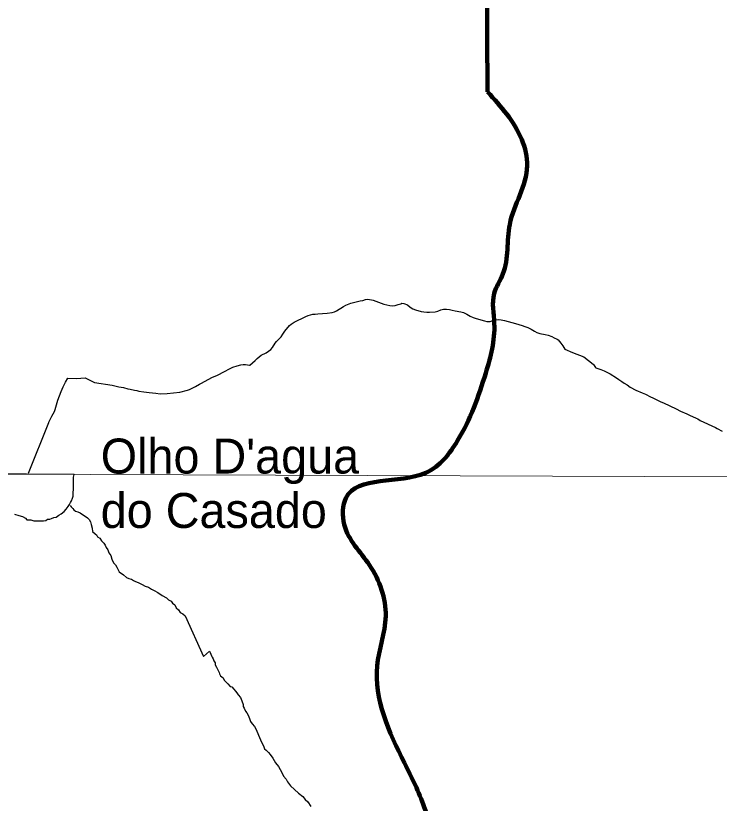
# Model space of a CAD drawing. Extents: x 553962 to 842807, y 8883888 to 9032388.
# Drawn here: x 628127 to 638188, y 8944931 to 8956199 of the extents above; entities that cross this region are included whole.
import ezdxf

# ---------------------------------------------------------------- set-up
doc = ezdxf.new("R2010")
doc.units = 0
doc.header["$LTSCALE"] = 20
for name, color, linetype, lineweight in [('1', 7, 'Continuous', 13), ('12', 7, 'Continuous', 25), ('21', 7, 'Continuous', 25), ('9', 7, 'Continuous', 90)]:
    doc.layers.add(name, color=color, linetype=linetype, lineweight=lineweight)
doc.layers.add('41', color=7, linetype='Continuous')

msp = doc.modelspace()

# ---------------------------------------------------------------- linework, layer by layer
at = {"layer": '1'}
msp.add_line((565315.27, 8949866.81), (791497.68, 8949052.23), dxfattribs=at)
at = {"layer": '12'}
for points in [[(631977.14, 8951685.31), (632043.77, 8951765.54), (632068.08, 8951787.61), (632108.71, 8951813.71), (632273.33, 8951897.11), (632308.21, 8951910.18), (632340.39, 8951920.25), (632377.33, 8951927.32), (632410.52, 8951931.38), (632445.52, 8951933.43), (632582.96, 8951943.67), (632651.08, 8951951.79), (632683.27, 8951961.85), (632714.52, 8951977.93), (632813.64, 8952039.18), (632846.33, 8952056.26), (632917.71, 8952084.42), (633052.14, 8952118.68), (633089.08, 8952126.75), (633126.77, 8952136.83), (633162.73, 8952142.23)], [(633162.73, 8952142.23), (633240.96, 8952131), (633351.39, 8952085.1), (633389.39, 8952073.15), (633475.96, 8952053.25), (633512.33, 8952049.3), (633554.83, 8952055.38), (633594.52, 8952068.46), (633634.89, 8952078.54), (633648.77, 8952084.57), (633676.33, 8952083.62), (633727.39, 8952060.66), (633770.14, 8952027.68), (633804.08, 8952004.69), (633842.58, 8951989.73), (633923.58, 8951967.83), (633963.14, 8951960.88), (634004.52, 8951957.94), (634042.96, 8951958), (634125.08, 8951962.14), (634165.58, 8951972.22), (634207.02, 8951990.31), (634246.58, 8951999.39), (634287.96, 8952002.46), (634328.46, 8951997.51), (634368.89, 8951987.56), (634409.46, 8951974.61), (634490.39, 8951962.71), (634530.83, 8951952.76), (634579.83, 8951930.81), (634627.89, 8951901.84), (634668.14, 8951883.87), (634709.77, 8951868.92), (634829.27, 8951833.05), (634866.14, 8951824.09)], [(634866.14, 8951824.09), (634873.39, 8951824.1), (634910.21, 8951826.17), (634950.71, 8951837.25), (634989.14, 8951847.32), (635028.08, 8951852.39), (635071.27, 8951849.46), (635114.64, 8951840.51), (635272.58, 8951793.69), (635367.21, 8951768.8), (635408.89, 8951751.84), (635451.39, 8951736.88), (635498.58, 8951712.92), (635544.21, 8951683.95), (635579.39, 8951665.97), (635619.89, 8951654.02), (635700.83, 8951640.13), (635740.46, 8951628.17), (635792.39, 8951609.22), (635828.71, 8951590.25), (635872.46, 8951570.29), (635883.64, 8951562.29), (635922.39, 8951513.28), (635950.14, 8951475.26), (635979.58, 8951429.24), (636087.14, 8951379.33), (636253.14, 8951319.5), (636386.46, 8951215.55), (636391.71, 8951209.55), (636419.71, 8951164.52), (636421.71, 8951160.52), (636421.71, 8951160.5), (636421.71, 8951160.52)], [(628309.19, 8949653.44), (628599.71, 8950377.92), (628601.33, 8950384.94), (628641.39, 8950470.13), (628663.02, 8950503.22), (628681.27, 8950538.3), (628691.77, 8950567.36), (628700.39, 8950599.43), (628710.96, 8950631.49), (628727.33, 8950696.62), (628774.64, 8950822.89), (628788.89, 8950855.97), (628806.89, 8950888.05), (628840.77, 8950956.21), (628872.21, 8951013.35), (628996.89, 8951009.54), (629121.21, 8951016.75), (629253.83, 8950950.85), (629505.89, 8950912.19), (629601.83, 8950889.31), (629665.71, 8950879.39), (629728.83, 8950861.46), (629762.52, 8950857.51), (629825.58, 8950843.59), (629857.52, 8950834.63), (629889.52, 8950829.67), (629956.46, 8950815.75), (630035.27, 8950806.86), (630130.21, 8950799), (630192.33, 8950791.09), (630294.14, 8950795.25), (630475.33, 8950814.57), (630582.08, 8950842.78), (630610.83, 8950852.85), (630639.64, 8950867.91), (630696.46, 8950894.05), (630755.08, 8950927.19), (630784.02, 8950940.26), (630880.83, 8950995.5), (630942.27, 8951026.64), (631001.89, 8951051.77), (631119.89, 8951113.06), (631172.39, 8951142.19), (631232.08, 8951169.32), (631292.58, 8951189.45), (631346.58, 8951202.56), (631380.39, 8951208.62), (631413.71, 8951209.67), (631469.39, 8951200.75), (631474.58, 8951200.75), (631552.96, 8951267.98), (631580.96, 8951297.07), (631608.21, 8951320.15), (631637.46, 8951342.23), (631707.21, 8951377.4), (631776.39, 8951422.58), (631796.77, 8951451.66), (631836.14, 8951514.82), (631854.46, 8951538.88), (631890.14, 8951572.99), (631921.39, 8951606.09), (631949.08, 8951643.2), (631977.14, 8951685.31), (631977.14, 8951685.31)], [(636421.71, 8951160.52), (636492.64, 8951137.59), (636543.77, 8951117.64), (636626.89, 8951075.71), (636719.46, 8951017.77), (636751.46, 8950995.78), (636795.33, 8950967.81), (636826.08, 8950942.82), (636870.71, 8950918.85), (636915.39, 8950886.87), (636996.52, 8950842.93), (637085.14, 8950803.01), (637131.58, 8950784.05), (637204.67, 8950745.08)], [(637204.67, 8950745.08), (637236.39, 8950731.89), (637342.11, 8950681.19), (637402.46, 8950654.15), (637429.51, 8950639.72), (637442.23, 8950635.25), (637481.26, 8950617.94), (637571.46, 8950574.99), (637632.67, 8950543.33), (637724.17, 8950501.81), (637761.89, 8950483.02), (637855.75, 8950440.22), (637882.16, 8950429.63), (637917.44, 8950409.53), (638133.95, 8950306.46), (638157.9, 8950291.91), (638228.47, 8950253.87)], [(628906.42, 8949193.41), (628921.28, 8949173.29), (628943.61, 8949150.61), (628955.96, 8949130.5), (628983.33, 8949110.29), (629015.78, 8949102.56), (629048.16, 8949084.82), (629080.52, 8949064.58), (629117.82, 8949036.8), (629155.19, 8949016.52), (629177.5, 8948991.34), (629197.27, 8948958.66), (629204.48, 8948921.06), (629221.57, 8948865.87), (629226.23, 8948820.78), (629261, 8948788), (629283.37, 8948770.33), (629298.17, 8948742.69), (629330.55, 8948724.95), (629352.77, 8948687.25), (629385.04, 8948654.49), (629404.81, 8948624.32), (629422.07, 8948591.66), (629441.82, 8948556.48), (629459.02, 8948516.31), (629488.7, 8948473.55), (629503.33, 8948423.38), (629522.94, 8948370.68), (629552.74, 8948342.94), (629572.48, 8948307.76), (629604.48, 8948239.96), (629669.18, 8948196.97)], [(629669.18, 8948196.97), (629708.91, 8948159.15), (629743.83, 8948146.4), (629783.77, 8948136.13), (629808.64, 8948118.44), (629841.06, 8948105.71), (629875.94, 8948087.95), (629898.37, 8948077.78), (629935.77, 8948062.52), (629978.08, 8948034.7), (630025.51, 8948021.87), (630067.81, 8947994.05), (630107.7, 8947976.26), (630157.49, 8947945.89), (630219.71, 8947905.42), (630281.98, 8947872.46), (630311.75, 8947839.72), (630351.65, 8947824.43), (630368.91, 8947791.77), (630401.25, 8947769.03), (630420.95, 8947728.84), (630455.72, 8947696.07), (630480.46, 8947660.85), (630515.32, 8947640.59), (630547.61, 8947610.34), (630810.81, 8947030.28)], [(630810.81, 8947030.28), (630898.94, 8947107.31), (630908.79, 8947087.21), (630916.1, 8947062.13), (630925.95, 8947042.04), (630938.28, 8947019.42), (630948.14, 8946999.33), (630960.41, 8946969.21), (630977.71, 8946941.56), (630979.96, 8946908.99), (630999.74, 8946878.82), (631016.95, 8946838.65), (631034.19, 8946803.49), (631041.54, 8946783.41), (631056.33, 8946755.77), (631091.1, 8946722.99), (631108.38, 8946692.84), (631140.62, 8946657.58), (631160.48, 8946637.42), (631192.71, 8946599.65), (631215.18, 8946594.49), (631247.46, 8946564.24), (631269.74, 8946534.05), (631289.58, 8946511.39), (631306.87, 8946483.73), (631339.08, 8946443.46), (631358.73, 8946395.76), (631378.36, 8946345.57), (631380.61, 8946313.01), (631395.46, 8946292.88), (631412.64, 8946250.21), (631432.44, 8946222.53), (631452.2, 8946189.86), (631469.37, 8946144.68), (631486.55, 8946102.01), (631508.81, 8946069.31), (631541.02, 8946029.05), (631560.76, 8945993.86), (631627.11, 8945838.21)], [(631627.11, 8945838.21), (631649.21, 8945785.49), (631668.97, 8945752.81), (631686.16, 8945710.14), (631706.01, 8945689.98), (631740.76, 8945654.69), (631765.56, 8945626.99), (631805.19, 8945576.66), (631822.46, 8945544), (631842.21, 8945511.32), (631884.31, 8945455.97), (631906.5, 8945413.26), (631938.61, 8945360.48), (631958.29, 8945317.78), (631995.48, 8945274.98), (632015.19, 8945234.79), (632057.3, 8945181.94), (632111.91, 8945126.5), (632171.55, 8945076.03), (632231.21, 8945028.07), (632268.38, 8944982.76), (632303.17, 8944952.49), (632347.65, 8944882.1)]]:
    msp.add_lwpolyline(points, dxfattribs=at)
at = {"layer": '21'}
msp.add_lwpolyline([(628110.58, 8949066.73), (628172.96, 8949048.88), (628225.36, 8949033.59), (628265.21, 8949010.86), (628287.56, 8948988.22), (628315.06, 8948988.07), (628342.54, 8948985.42), (628384.94, 8948970.19), (628409.94, 8948970.06), (628442.44, 8948969.89), (628474.94, 8948969.71), (628499.94, 8948969.58), (628524.96, 8948971.95), (628554.99, 8948976.79), (628582.61, 8948994.17), (628612.61, 8948994.01), (628640.19, 8949006.37), (628670.29, 8949021.23), (628702.81, 8949023.56), (628745.51, 8949053.36), (628778.14, 8949073.21), (628818.36, 8949105.53), (628848.6, 8949140.4), (628878.84, 8949175.27), (628896.54, 8949205.21), (628909.22, 8949232.66), (628924.39, 8949257.61), (628937.16, 8949297.58), (628949.85, 8949325.03), (628950.03, 8949352.57), (628950.27, 8949387.59), (628952.94, 8949412.6), (628953.28, 8949462.65), (628953.41, 8949482.67), (628953.67, 8949520.2), (628953.8, 8949540.22), (628953.95, 8949562.74), (628954.17, 8949595.27), (628960.22, 8949636.38), (627600.12, 8949642.89)], dxfattribs=at)
at = {"layer": '9'}
msp.add_lwpolyline([(637260.63, 8972975.84), (637076.77, 8961505.69), (634855.74, 8958401.33), (634875.26, 8955110.32)], dxfattribs=at)
for points in [[(637260.63, 8972975.84), (641524.45, 8971056.24), (652526.05, 8965412.73), (653164.33, 8965062.83), (670790.48, 8953770.1), (686194.04, 8943929.95), (696283.29, 8937647.07)], [(630387.41, 8939797.8), (630434.25, 8940142.1), (630686.47, 8940523.63), (631192.1, 8941084.18), (631927.52, 8941519.78), (632256.08, 8941901.85), (632534.19, 8942207.62), (633141.92, 8942718.26), (633623.16, 8943101.43), (634002.92, 8943433.23), (634103.5, 8943636.48), (634126.4, 8944067.02), (633968.91, 8944876.03), (633685.24, 8945506.93), (633295.28, 8946896.57), (633418.31, 8947606.31), (633184.94, 8948338.83), (632825.23, 8948918.56), (632848.42, 8949298.47), (633991.44, 8949661.01), (634446.78, 8950119.94), (634848.23, 8951084.81), (634971.26, 8951794.54), (634968.71, 8952224.91), (635094.29, 8952504.28), (635191.88, 8953213.83), (635441.4, 8954051.05), (635362.8, 8954430.24), (634875.26, 8955110.32)]]:
    msp.add_spline(points, degree=3, dxfattribs=at)

# ---------------------------------------------------------------- texts
at = {"layer": '41'}
for s, p in [("Olho D'agua", (629342.18, 8949648.85)), ('do Casado', (629342.18, 8948869.84))]:
    msp.add_text(s, height=500, dxfattribs=at).set_placement(p)

doc.saveas('drawing.dxf')
